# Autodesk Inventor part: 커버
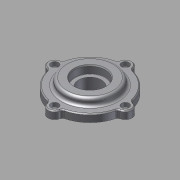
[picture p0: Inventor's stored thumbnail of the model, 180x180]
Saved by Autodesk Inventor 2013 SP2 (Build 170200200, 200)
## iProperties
Company: 한국ATC센터
Created: 2015-12
Part Number: 커버
Document SubType Name: Modeling
Designer: mdu
Density: 1 g/cm^3
Material: 일반
Author: mdu
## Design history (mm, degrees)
sketch "스케치1"
  geometry: C1 r 1.621 at (0, 6.75) reference; C2 r 1.621 at (-37, -30.25) reference; C3 r 1.621 at (0, -67.25) reference; C4 r 1.621 at (37, -30.25) reference; C5 r 10 at (0, -30.25) reference; C6 r 12 at (0, -30.25); C7 r 24.5 at (0, -30.25) reference; A1 r 3 centre (-38.77, -20.408) between (-38.239, -23.361) and (-35.862, -21.146) reference; A2 r 7 centre (-37, -30.25) between (-38.239, -23.361) and (-38.239, -37.139) reference; A3 r 3 centre (-38.77, -40.092) between (-35.862, -39.354) and (-38.239, -37.139) reference; A4 r 37 centre (0, -30.25) between (-35.862, -39.354) and (-9.104, -66.113) reference; A5 r 3 centre (-9.842, -69.02) between (-6.889, -68.489) and (-9.104, -66.113) reference; A6 r 7 centre (0, -67.25) between (-6.889, -68.489) and (6.889, -68.489) reference; A7 r 3 centre (9.842, -69.02) between (9.104, -66.112) and (6.889, -68.489) reference; A8 r 37 centre (0, -30.25) between (9.104, -66.112) and (35.863, -39.354) reference; A9 r 3 centre (38.77, -40.092) between (38.239, -37.139) and (35.863, -39.354) reference; A10 r 7 centre (37, -30.25) between (38.239, -37.139) and (38.239, -23.361) reference; A11 r 3 centre (38.77, -20.408) between (35.863, -21.146) and (38.239, -23.361) reference; A12 r 37 centre (0, -30.25) between (35.863, -21.146) and (9.104, 5.612) reference; A13 r 3 centre (9.842, 8.52) between (6.889, 7.989) and (9.104, 5.612) reference; A14 r 7 centre (0, 6.75) between (6.889, 7.989) and (-6.889, 7.989) reference; A15 r 3 centre (-9.842, 8.52) between (-9.104, 5.612) and (-6.889, 7.989) reference; A16 r 37 centre (0, -30.25) between (-9.104, 5.612) and (-35.862, -21.146) reference; 1 further point
  constraints: 1 centre point, 1 coincident
  dimensions: "d2" = 2 radial gap between concentric circles of C6 C5
extrude "돌출1" new body sketch "스케치1" distance "d0" = 8; taper "d1" = 0 deg
sketch "스케치2"
  geometry: C1 r 23.5 at (0, -30.25) reference; C2 r 12 at (0, -30.25) reference; 1 further point
extrude "돌출2" join sketch "스케치2" distance "d4" = 5; taper "d5" = 0 deg
sketch "스케치3"
  geometry: C1 r 23.5 at (0, 0) reference; C2 r 20.5 at (0, 0); 1 further point
  constraints: 1 centre point
  dimensions: "d6" = 3 radial gap between concentric circles of C2 C1
node "작업 평면1"
extrude "돌출3" join sketch "스케치3" stored distance "d7" = 5; taper "d8" = 0 deg
fillet "모깎기1" dims "d9" = 3
sketch "스케치4"
  geometry: C1 r 12 at (0, -30.25) reference; C2 r 27 at (0, -30.25); 1 further point
  constraints: 1 centre point
  dimensions: "d10" = 15 radial gap between concentric circles of C1 C2
extrude "돌출4" join sketch "스케치4" distance "d11" = 7; taper "d12" = 0 deg
fillet "모깎기2" dims "d13" = 3
chamfer "모따기1" distance "d14" = 1; stored, may be unused: second distance "d15" = 2, angle "d16" = 45 deg
node "작업점1"
  node "작업축1"
chamfer "모따기2" distance "d24" = 1; stored, may be unused: second distance "d25" = 2, angle "d26" = 45 deg
hole "구멍6" diameter "d43" = 4.5; stored, may be unused: countersink angle "d47" = 90 deg, drill point angle "d49" = 118 deg; dims "d41" = 10, "d42" = 10, "d44" = 6, "d45" = 8, "d46" = 4.4, "d48" = 8
sketch "스케치8"
  geometry: C1 r 12 at (0, 0) reference; C2 r 16 at (0, 0); 1 further point
  constraints: 1 centre point, 1 coincident
  dimensions: "d53" = 32 diameter of C2
extrude "돌출5" cut sketch "스케치8" distance "d54" = 8.3; taper "d55" = 0 deg
fillet "모깎기3" dims "d56" = 0.3
chamfer "모따기3" distance "d57" = 1.2; stored, may be unused: second distance "d58" = 2, angle "d59" = 30 deg
node "솔리드1"
pattern_circular "원형 패턴1" dims angle "d51" = 360 deg
node "참조1"
node "참조2"
